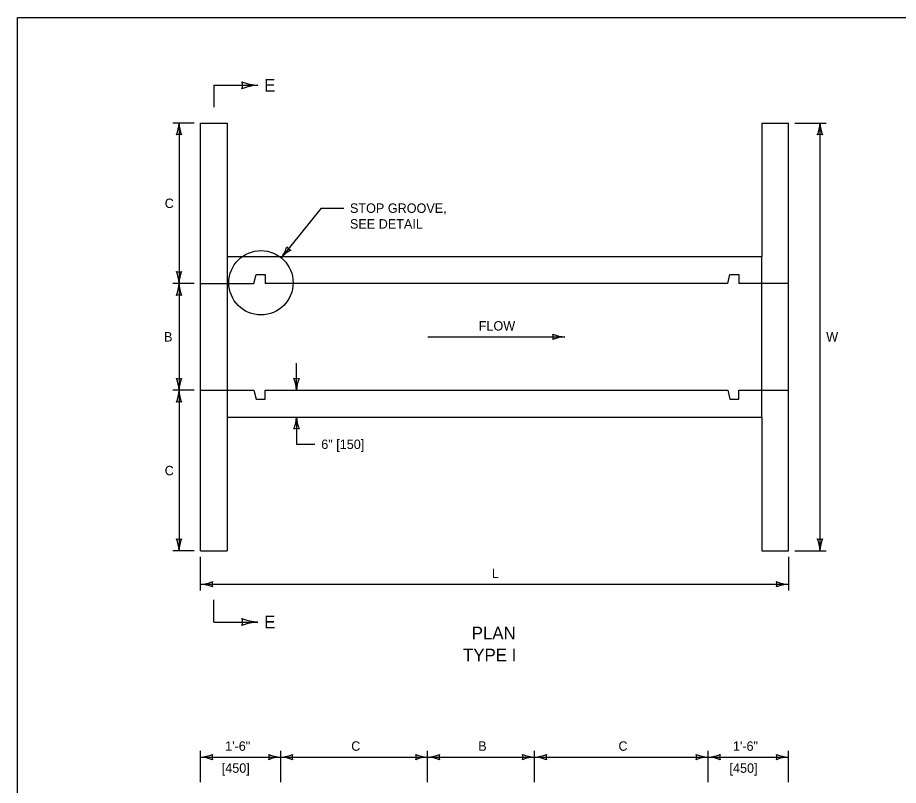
# Model space of a CAD drawing. Extents: x 49991.4 to 50021, y 49987.6 to 50011.4.
# Drawn here: x 49999.38 to 50004.99, y 49994.12 to 49999 of the extents above; entities that cross this region are included whole.
import ezdxf

# ---------------------------------------------------------------- set-up
doc = ezdxf.new("R2010")
doc.units = 0
for name, color, linetype in [('Level 1', 7, 'Continuous'), ('Level 2', 7, 'Continuous'), ('Level 3', 7, 'Continuous'), ('Level 4', 7, 'Continuous'), ('Level 6', 7, 'Continuous')]:
    doc.layers.add(name, color=color, linetype=linetype)

msp = doc.modelspace()

# ---------------------------------------------------------------- linework, layer by layer
at = {"layer": 'Level 1'}
for p, q in [((50000.547, 49995.6089), (50000.547, 49998.3289)), ((50000.547, 49998.3289), (50000.7168, 49998.3289)), ((50000.7168, 49998.3289), (50000.7168, 49997.4789)), ((50004.117, 49998.3289), (50004.287, 49998.3289)), ((50004.117, 49998.3289), (50004.117, 49997.4789)), ((50004.287, 49995.6089), (50004.287, 49998.3289)), ((50000.7168, 49997.4789), (50004.117, 49997.4789)), ((50000.8868, 49997.3089), (50000.901, 49997.3655)), ((50000.901, 49997.3655), (50000.9576, 49997.3655)), ((50000.9576, 49997.3655), (50000.9576, 49997.3089)), ((50003.9002, 49997.3089), (50003.9144, 49997.3655)), ((50003.9144, 49997.3655), (50003.971, 49997.3655)), ((50003.971, 49997.3655), (50003.971, 49997.3089)), ((50000.547, 49997.3089), (50000.8868, 49997.3089)), ((50003.9002, 49997.3089), (50000.9576, 49997.3089)), ((50004.287, 49997.3089), (50003.971, 49997.3089)), ((50000.547, 49996.6289), (50000.8868, 49996.6289)), ((50000.8868, 49996.6289), (50000.901, 49996.5723)), ((50000.9576, 49996.5723), (50000.9576, 49996.6289)), ((50000.9576, 49996.6289), (50003.9002, 49996.6289)), ((50003.9002, 49996.6289), (50003.9144, 49996.5723)), ((50003.971, 49996.6289), (50004.287, 49996.6289)), ((50003.971, 49996.5723), (50003.971, 49996.6289)), ((50000.901, 49996.5723), (50000.9576, 49996.5723)), ((50003.9144, 49996.5723), (50003.971, 49996.5723)), ((50000.7168, 49996.4589), (50000.7168, 49995.6089)), ((50000.7168, 49996.4589), (50004.117, 49996.4589)), ((50004.117, 49996.4589), (50004.117, 49995.6089)), ((50000.547, 49995.6089), (50000.7168, 49995.6089)), ((50004.117, 49995.6089), (50004.287, 49995.6089))]:
    msp.add_line(p, q, dxfattribs=at)
msp.add_lwpolyline([(49999.3835, 49998.9992), (50016.7501, 49998.9992), (50016.7501, 49987.7988), (49999.3835, 49987.7988)], close=True, dxfattribs=at)
at = {"layer": 'Level 3'}
for p, q in [((50000.507, 49998.3289), (50000.3702, 49998.3289)), ((50000.4102, 49998.3289), (50000.4102, 49995.6089)), ((50004.327, 49998.3289), (50004.527, 49998.3289)), ((50004.487, 49998.3289), (50004.487, 49995.6089)), ((50001.3153, 49997.7874), (50001.0602, 49997.472)), ((50001.3153, 49997.7874), (50001.4576, 49997.7874)), ((50000.507, 49997.3089), (50000.3702, 49997.3089)), ((50001.9937, 49996.9689), (50002.8641, 49996.9689)), ((50001.1576, 49996.6289), (50001.1576, 49996.8023)), ((50000.507, 49996.6289), (50000.3702, 49996.6289)), ((50001.1576, 49996.4589), (50001.1576, 49996.2855)), ((50001.1576, 49996.2855), (50001.2749, 49996.2855)), ((50000.507, 49995.6089), (50000.3702, 49995.6089)), ((50004.327, 49995.6089), (50004.527, 49995.6089)), ((50000.547, 49995.3553), (50000.547, 49995.5689)), ((50004.287, 49995.5689), (50004.287, 49995.3553)), ((50000.547, 49995.3953), (50004.287, 49995.3953)), ((50000.5469, 49994.1362), (50000.5469, 49994.3362)), ((50001.0569, 49994.1362), (50001.0569, 49994.3362)), ((50001.9918, 49994.1362), (50001.9918, 49994.3362)), ((50002.6718, 49994.1362), (50002.6718, 49994.3362)), ((50003.7768, 49994.1362), (50003.7768, 49994.3362)), ((50004.2868, 49994.1362), (50004.2868, 49994.3362)), ((50000.5469, 49994.2962), (50004.2868, 49994.2962))]:
    msp.add_line(p, q, dxfattribs=at)
msp.add_circle((50000.9316, 49997.3129), 0.2046, dxfattribs=at)
for centre, radius, start, end in [((50000.9241, 49998.8651), 0.2964, 247.456, 267.6395), ((50000.7409, 49998.5689), 0.073, 342.1388, 17.8612), ((50000.9272, 49998.2586), 0.3107, 92.8273, 112.0772), ((50000.1881, 49998.3381), 0.2223, 337.456, 357.6395), ((50000.6429, 49998.3404), 0.233, 182.8273, 202.0772), ((50004.2649, 49998.3381), 0.2223, 337.456, 357.6395), ((50004.7197, 49998.3404), 0.233, 182.8273, 202.0772), ((50000.4102, 49998.2007), 0.0548, 72.1388, 107.8612), ((50004.487, 49998.2007), 0.0548, 72.1388, 107.8612), ((50000.8721, 49997.6094), 0.233, 323.8627, 343.1126), ((50001.2272, 49997.3252), 0.2223, 118.4914, 138.6749), ((50001.1409, 49997.5717), 0.0548, 213.1742, 248.8966), ((50000.1881, 49997.2997), 0.2223, 2.3605, 22.544), ((50000.4102, 49997.4371), 0.0548, 252.1388, 287.8612), ((50000.6429, 49997.2974), 0.233, 157.9228, 177.1727), ((50000.1881, 49997.3181), 0.2223, 337.456, 357.6395), ((50000.6429, 49997.3204), 0.233, 182.8273, 202.0772), ((50000.4102, 49997.1807), 0.0548, 72.1388, 107.8612), ((50002.8733, 49997.191), 0.2223, 247.456, 267.6395), ((50002.7359, 49996.9689), 0.0548, 342.1388, 17.8612), ((50002.8756, 49996.7362), 0.233, 92.8273, 112.0772), ((50000.1881, 49996.6197), 0.2223, 2.3605, 22.544), ((50000.4102, 49996.7571), 0.0548, 252.1388, 287.8612), ((50000.6429, 49996.6174), 0.233, 157.9228, 177.1727), ((50000.9355, 49996.6197), 0.2223, 2.3605, 22.544), ((50001.1576, 49996.7571), 0.0548, 252.1388, 287.8612), ((50001.3903, 49996.6174), 0.233, 157.9228, 177.1727), ((50000.1881, 49996.6381), 0.2223, 337.456, 357.6395), ((50000.6429, 49996.6404), 0.233, 182.8273, 202.0772), ((50000.4102, 49996.5007), 0.0548, 72.1388, 107.8612), ((50000.9355, 49996.4681), 0.2223, 337.456, 357.6395), ((50001.3903, 49996.4704), 0.233, 182.8273, 202.0772), ((50001.1576, 49996.3307), 0.0548, 72.1388, 107.8612), ((50000.1881, 49995.5997), 0.2223, 2.3605, 22.544), ((50000.4102, 49995.7371), 0.0548, 252.1388, 287.8612), ((50000.6429, 49995.5974), 0.233, 157.9228, 177.1727), ((50004.2649, 49995.5997), 0.2223, 2.3605, 22.544), ((50004.487, 49995.7371), 0.0548, 252.1388, 287.8612), ((50004.7197, 49995.5974), 0.233, 157.9228, 177.1727), ((50000.5378, 49995.6174), 0.2223, 272.3605, 292.544), ((50000.5355, 49995.1626), 0.233, 67.9228, 87.1727), ((50000.6752, 49995.3953), 0.0548, 162.1388, 197.8612), ((50004.2962, 49995.6174), 0.2223, 247.456, 267.6395), ((50004.1588, 49995.3953), 0.0548, 342.1388, 17.8612), ((50004.2985, 49995.1626), 0.233, 92.8273, 112.0772), ((50000.7409, 49995.1553), 0.073, 342.1388, 17.8612), ((50000.9272, 49995.4656), 0.3107, 247.9228, 267.1727), ((50000.9241, 49994.8591), 0.2964, 92.3605, 112.544), ((50000.5377, 49994.5183), 0.2223, 272.3605, 292.544), ((50000.6751, 49994.2962), 0.0548, 162.1388, 197.8612), ((50000.9287, 49994.2962), 0.0548, 342.1388, 17.8612), ((50001.0684, 49994.5289), 0.233, 247.9228, 267.1727), ((50001.0477, 49994.5183), 0.2223, 272.3605, 292.544), ((50001.1851, 49994.2962), 0.0548, 162.1388, 197.8612), ((50001.8636, 49994.2962), 0.0548, 342.1388, 17.8612), ((50002.0033, 49994.5289), 0.233, 247.9228, 267.1727), ((50001.9826, 49994.5183), 0.2223, 272.3605, 292.544), ((50002.12, 49994.2962), 0.0548, 162.1388, 197.8612), ((50002.5436, 49994.2962), 0.0548, 342.1388, 17.8612), ((50002.6833, 49994.5289), 0.233, 247.9228, 267.1727), ((50002.6626, 49994.5183), 0.2223, 272.3605, 292.544), ((50002.8, 49994.2962), 0.0548, 162.1388, 197.8612), ((50003.6486, 49994.2962), 0.0548, 342.1388, 17.8612), ((50003.7883, 49994.5289), 0.233, 247.9228, 267.1727), ((50003.7676, 49994.5183), 0.2223, 272.3605, 292.544), ((50003.905, 49994.2962), 0.0548, 162.1388, 197.8612), ((50004.1586, 49994.2962), 0.0548, 342.1388, 17.8612), ((50004.2983, 49994.5289), 0.233, 247.9228, 267.1727), ((50000.5354, 49994.0635), 0.233, 67.9228, 87.1727), ((50001.0661, 49994.0741), 0.2223, 92.3605, 112.544), ((50001.0454, 49994.0635), 0.233, 67.9228, 87.1727), ((50002.001, 49994.0741), 0.2223, 92.3605, 112.544), ((50001.9803, 49994.0635), 0.233, 67.9228, 87.1727), ((50002.681, 49994.0741), 0.2223, 92.3605, 112.544), ((50002.6603, 49994.0635), 0.233, 67.9228, 87.1727), ((50003.786, 49994.0741), 0.2223, 92.3605, 112.544), ((50003.7653, 49994.0635), 0.233, 67.9228, 87.1727), ((50004.296, 49994.0741), 0.2223, 92.3605, 112.544)]:
    msp.add_arc(centre, radius, start, end, dxfattribs=at)
at = {"layer": 'Level 4'}
for p, q in [((50000.7168, 49997.4789), (50000.7168, 49996.4589)), ((50004.117, 49997.4789), (50004.117, 49997.4789)), ((50004.117, 49996.4589), (50004.117, 49997.4789))]:
    msp.add_line(p, q, dxfattribs=at)
at = {"layer": 'Level 6'}
for p, q in [((50000.6319, 49998.5689), (50000.9119, 49998.5689)), ((50000.6319, 49998.5689), (50000.6319, 49998.4289)), ((50000.6319, 49995.1553), (50000.6319, 49995.2953)), ((50000.6319, 49995.1553), (50000.9119, 49995.1553))]:
    msp.add_line(p, q, dxfattribs=at)

# ---------------------------------------------------------------- texts
at = {"layer": 'Level 2'}
for s, height, p in [('E', 0.08, (50000.9519, 49998.5289)), ('C', 0.06, (50000.3192, 49997.7882)), ('STOP GROOVE,', 0.06, (50001.4976, 49997.7574)), ('SEE DETAIL', 0.06, (50001.4976, 49997.6574)), ('FLOW', 0.06, (50002.3167, 49997.0089)), ('B', 0.06, (50000.3147, 49996.9389)), ('W', 0.06, (50004.527, 49996.9389)), ('6" [150]', 0.06, (50001.3149, 49996.2555)), ('C', 0.06, (50000.3192, 49996.0883)), ('L', 0.06, (50002.4, 49995.4353)), ('E', 0.08, (50000.9519, 49995.1153)), ('PLAN', 0.08, (50002.2721, 49995.0453)), ('TYPE I', 0.08, (50002.2169, 49994.9053)), ('1\'-6"', 0.06, (50000.7036, 49994.3362)), ('C', 0.06, (50001.5057, 49994.3362)), ('B', 0.06, (50002.3132, 49994.3362)), ('C', 0.06, (50003.2057, 49994.3362)), ('1\'-6"', 0.06, (50003.9335, 49994.3362)), ('[450]', 0.06, (50000.6818, 49994.1962)), ('[450]', 0.06, (50003.9117, 49994.1962))]:
    msp.add_text(s, height=height, dxfattribs=at).set_placement(p)

doc.saveas('drawing.dxf')
